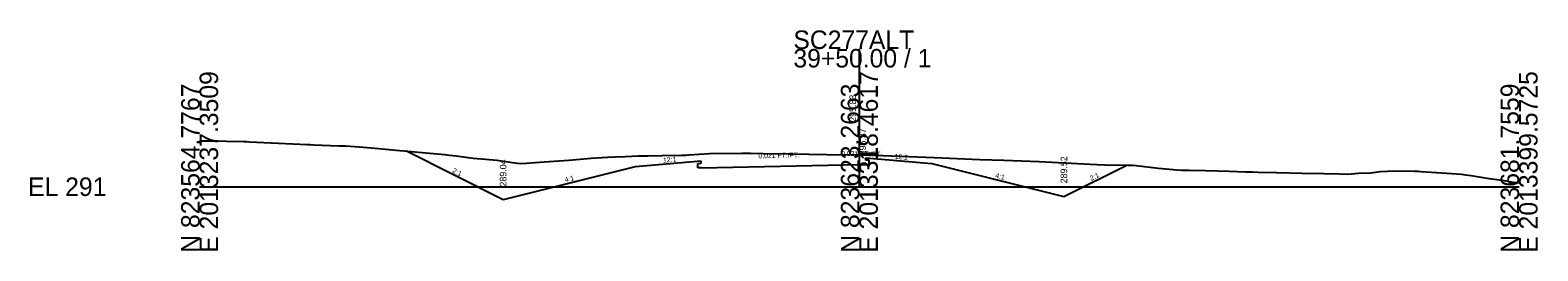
# Model space of a CAD drawing. Extents: x 205929 to 2357175, y -1785700 to 827636.
# Drawn here: x 2018394.5 to 2018623, y 827534.6 to 827567.9 of the extents above; entities that cross this region are included whole.
import ezdxf

# ---------------------------------------------------------------- set-up
doc = ezdxf.new("R2010")
doc.units = 0
for name, color, linetype in [('RD_GPK_XS_Cell', 7, 'Continuous'), ('RD_XS_Base', 7, 'Continuous'), ('RD_XS_EarthShd', 7, 'Continuous'), ('RD_XS_ExGround', 7, 'Continuous'), ('RD_XS_Pave', 7, 'Continuous'), ('RD_XS_TieSlope', 7, 'Continuous'), ('RD_XS_TX_Elev_EX', 7, 'Continuous'), ('RD_XS_TX_Elev_PR', 7, 'Continuous'), ('RD_XS_TX_ShdSlope', 7, 'Continuous'), ('RD_XS_TX_Slope', 7, 'Continuous')]:
    doc.layers.add(name, color=color, linetype=linetype)

msp = doc.modelspace()

# ---------------------------------------------------------------- linework, layer by layer
at = {"layer": 'RD_GPK_XS_Cell'}
for p, q in [((2018520.17, 827544.26), (2018520.17, 827565.1)), ((2018420.17, 827544.26), (2018520.17, 827544.26)), ((2018520.17, 827544.26), (2018620.17, 827544.26))]:
    msp.add_line(p, q, dxfattribs=at)
at = {"layer": 'RD_XS_Base'}
for p, q in [((2018496.17, 827547.13), (2018520.17, 827547.63)), ((2018520.17, 827547.63), (2018521.17, 827547.61))]:
    msp.add_line(p, q, dxfattribs=at)
at = {"layer": 'RD_XS_EarthShd'}
for p, q in [((2018521.17, 827548.61), (2018531.17, 827547.77)), ((2018496.17, 827548.13), (2018486.17, 827547.29))]:
    msp.add_line(p, q, dxfattribs=at)
at = {"layer": 'RD_XS_ExGround'}
msp.add_lwpolyline([(2018420.17, 827551.2), (2018421.59, 827551.18), (2018426.87, 827551.11), (2018427.33, 827551.08), (2018427.71, 827551.06), (2018432.12, 827550.84), (2018436.49, 827550.65), (2018436.94, 827550.63), (2018437.48, 827550.61), (2018440, 827550.51), (2018441.25, 827550.45), (2018441.92, 827550.43), (2018442.34, 827550.42), (2018444.99, 827550.26), (2018447.29, 827550.03), (2018450.49, 827549.76), (2018451.15, 827549.7), (2018454.46, 827549.41), (2018457.32, 827549.14), (2018458.04, 827549.05), (2018459.04, 827548.93), (2018461.62, 827548.6), (2018463.48, 827548.43), (2018465.2, 827548.26), (2018467.59, 827547.93), (2018468.78, 827547.78), (2018469.65, 827547.81), (2018472.37, 827548.04), (2018476.14, 827548.29), (2018479.53, 827548.56), (2018481.98, 827548.71), (2018483.11, 827548.79), (2018484.69, 827548.84), (2018486.69, 827548.93), (2018488.14, 827548.95), (2018490.27, 827548.96), (2018493.23, 827549.02), (2018493.86, 827549.03), (2018494.3, 827549.06), (2018497.44, 827549.31), (2018502.35, 827549.32), (2018503.66, 827549.33), (2018505.59, 827549.3), (2018509.38, 827549.25), (2018509.8, 827549.24), (2018515.23, 827549.15), (2018520.17, 827549.09), (2018521.16, 827549.08), (2018531.57, 827548.66), (2018538.44, 827548.4), (2018542.05, 827548.26), (2018547.44, 827548.06), (2018555.14, 827547.65), (2018556.18, 827547.6), (2018557.44, 827547.58), (2018560.9, 827547.53), (2018561.63, 827547.52), (2018562.11, 827547.49), (2018565.49, 827547.06), (2018568.28, 827546.83), (2018569.07, 827546.77), (2018570.17, 827546.76), (2018572.65, 827546.71), (2018574.44, 827546.66), (2018576.23, 827546.59), (2018578.72, 827546.53), (2018579.82, 827546.49), (2018580.61, 827546.48), (2018583.4, 827546.42), (2018587.27, 827546.3), (2018590.56, 827546.24), (2018592.94, 827546.21), (2018594.14, 827546.17), (2018595.82, 827546.3), (2018597.72, 827546.38), (2018599.1, 827546.57), (2018601.31, 827546.66), (2018604.36, 827546.61), (2018604.89, 827546.59), (2018605.26, 827546.56), (2018608.47, 827546.35), (2018611.43, 827546.14), (2018612.05, 827546.08), (2018612.91, 827545.95), (2018615.63, 827545.49), (2018617.59, 827545.23), (2018619.21, 827544.96), (2018620.17, 827544.83)], dxfattribs=at)
at = {"layer": 'RD_XS_Pave'}
for p, q in [((2018521.17, 827548.28), (2018521.17, 827548.61)), ((2018495.67, 827547.79), (2018496.17, 827547.8)), ((2018495.67, 827547.12), (2018495.67, 827547.79)), ((2018496.17, 827547.13), (2018495.67, 827547.12)), ((2018496.17, 827547.8), (2018496.17, 827548.13)), ((2018521.67, 827548.26), (2018521.17, 827548.28)), ((2018521.17, 827547.61), (2018521.67, 827547.59)), ((2018521.67, 827547.59), (2018521.67, 827548.26))]:
    msp.add_line(p, q, dxfattribs=at)
at = {"layer": 'RD_XS_TieSlope'}
for p, q in [((2018466.17, 827542.29), (2018451.4, 827549.68)), ((2018486.17, 827547.29), (2018466.17, 827542.29)), ((2018531.17, 827547.77), (2018551.17, 827542.77)), ((2018551.17, 827542.77), (2018560.7, 827547.53))]:
    msp.add_line(p, q, dxfattribs=at)

# ---------------------------------------------------------------- texts
at = {"layer": 'RD_GPK_XS_Cell'}
for s, p in [('SC277ALT', (2018510.17, 827565.1)), ('39+50.00 / 1', (2018510.17, 827562.3)), ('EL 291', (2018394.17, 827542.86))]:
    msp.add_text(s, height=2.8, dxfattribs=at).set_placement(p)
for s, p in [('E 2013237.3509', (2018422.97, 827534.26)), ('E 2013318.4617', (2018522.97, 827534.26)), ('E 2013399.5725', (2018622.97, 827534.26)), ('N 823564.7767', (2018420.17, 827534.26)), ('N 823623.2663', (2018520.17, 827534.26)), ('N 823681.7559', (2018620.17, 827534.26))]:
    msp.add_text(s, height=2.8, rotation=90, dxfattribs=at).set_placement(p)
at = {"layer": 'RD_XS_TX_Elev_EX'}
msp.add_text('295.83', height=1, rotation=90, dxfattribs=at).set_placement((2018519.67, 827554.09))
at = {"layer": 'RD_XS_TX_Elev_PR'}
for s, p in [(' 295.37', (2018521.17, 827548.63)), ('289.52', (2018551.67, 827544.77)), ('289.04', (2018466.67, 827544.29))]:
    msp.add_text(s, height=1, rotation=90, dxfattribs=at).set_placement(p)
at = {"layer": 'RD_XS_TX_ShdSlope'}
for rotation, p in [(4.7636, (2018490.44, 827547.9)), (355.2364, (2018525.48, 827548.5))]:
    msp.add_text('12:1', height=0.75, rotation=rotation, dxfattribs=at).set_placement(p)
at = {"layer": 'RD_XS_TX_Slope'}
for s, rotation, p in [('0.021 FT./FT.', 1.1916, (2018504.88, 827548.56)), ('0.021 FT./FT.', 358.8084, (2018517.39, 827548.93)), ('2:1', 333.4349, (2018458.39, 827546.46)), ('4:1', 345.9638, (2018540.72, 827545.64)), ('2:1', 26.5651, (2018555.32, 827545.12)), ('4:1', 14.0362, (2018475.6, 827544.91))]:
    msp.add_text(s, height=0.75, rotation=rotation, dxfattribs=at).set_placement(p)

doc.saveas('drawing.dxf')
